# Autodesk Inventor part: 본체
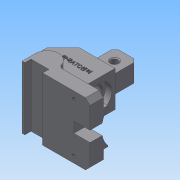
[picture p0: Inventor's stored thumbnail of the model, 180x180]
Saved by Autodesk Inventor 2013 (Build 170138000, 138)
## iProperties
Created: 2016-11
Part Number: 본체
Material: 일반
Document SubType Name: Modeling
Designer: Administrator
Density: 1 g/cm^3
Author: Administrator
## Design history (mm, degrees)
sketch "스케치1"
  geometry: L1 (-40.5, 0)-(-22.5, 18); L2 (-22.5, 18)-(17.5, 18); L3 (17.5, 18)-(17.5, -22); L4 (49.5, -30)-(-40.5, -30); L5 (-40.5, -30)-(-40.5, 0); L6 (49.5, -30)-(49.5, -22); L7 (49.5, -22)-(17.5, -22); 1 further point
  constraints: 14 end point, 4 perpendicular, 1 horizontal, 1 parallel
  dimensions: "d0" = 58 distance between parallel lines of L3 L5; "d2" = 48 distance between parallel lines of L4 L2; "d3" = 30 distance from line of L4 point (0, 0); "d4" = 17.5 distance from line of point (0, 0) L3; "d5" = 45 deg angle of L2 L1; "d6" = 18 horizontal distance of L1.start L1.end; "d28" = 90 distance of L4.start L4.end; "d30" = 40 distance between parallel lines of L7 L2
extrude "돌출1" new body sketch "스케치1" stored distance "d7" = 40; taper "d8" = 0 deg
sketch "스케치2"
  geometry: 2 further points
  constraints: 1 coincident
hole "구멍1" sketch "스케치2" at (20, 30) diameter "d10" = 20; stored, may be unused: countersink angle "d14" = 90 deg, drill point angle "d16" = 0 deg; dims "d11" = 6, "d12" = 29, "d13" = 7, "d15" = 8
sketch "스케치3"
  geometry: L1 (-26.5, -27)-(-26.5, -42); L2 (-26.5, -42)-(-23.5, -42); L3 (-23.5, -42)-(-23.5, -35); L4 (-23.5, -35)-(-3.5, -35); L5 (-3.5, -35)-(-3.5, -42); L6 (-3.5, -42)-(49.5, -42); L7 (49.5, -42)-(49.5, -27); L8 (49.5, -27)-(-0.5, -27); L9 (49.5, -22)-(49.5, -30) reference; A1 r 13 centre (-13.5, -27) between (-0.5, -27) and (-26.5, -27); 1 further point
  constraints: 16 end point, 3 collinear, 3 parallel, 3 perpendicular, 2 point on circle, 1 centre point, 1 horizontal alignment, 1 tangent, 1 vertical
  dimensions: "d17" = 26 diameter of A1; "d18" = 15 distance of L6.end L7.end; "d19" = 42 distance from line of L6 point (0, 0); "d20" = 20 distance between parallel lines of L5 L3; "d21" = 7 distance between parallel lines of L2 L4; "d22" = 3 distance of L1.end L2.end; "d25" = 63 distance from line of L7 A1.centre
extrude "돌출2" join sketch "스케치3" stored distance "d26" = 70; taper "d27" = 0 deg
sketch "스케치4"
  geometry: L1 (-15, -20)-(55, -20) reference; L2 (14, -6.373)-(14, -20); L3 (26, -6.373)-(26, -20); L4 (14, -20)-(26, -20); A1 r 29 centre (20, 22) between (26, -6.373) and (14, -6.373); 2 further points
  constraints: 6 end point, 2 perpendicular, 2 point on circle, 2 point on line, 1 centre point, 1 coincident, 1 collinear, 1 midpoint, 1 vertical alignment
  dimensions: "d31" = 58 diameter of A1; "d32" = 12 distance between parallel lines of L3 L2
extrude "돌출3" cut sketch "스케치4" distance "d33" = 18; taper "d34" = 0 deg
sketch "스케치5"
  geometry: L1 (-12.5, 48)-(12.5, 48); L2 (12.5, 48)-(12.5, 18); L3 (12.5, 18)-(-12.5, 18); L4 (-12.5, 18)-(-12.5, 48); L5 (-22.5, 18)-(17.5, 18) reference; L6 (49.5, -42)-(-3.5, -42) reference; 2 further points
  constraints: 8 end point, 2 parallel, 1 collinear, 1 horizontal, 1 midpoint, 1 perpendicular, 1 vertical alignment
  dimensions: "d35" = 25 distance of L1.start L1.end; "d37" = 90 distance between parallel lines of L6 L1
extrude "돌출4" join sketch "스케치5" stored distance "d38" = 20; taper "d39" = 0 deg
sketch "스케치6"
  geometry: C1 r 4 at (0, 35); 1 further point
  constraints: 1 centre point, 1 vertical alignment
  dimensions: "d40" = 8 diameter of C1; "d42" = 35 distance of point (0, 0) C1.centre
extrude "돌출5" cut sketch "스케치6" stored distance "d43" = 20; taper "d44" = 0 deg
chamfer "모따기1" distance "d45" = 4; stored, may be unused: second distance "d46" = 2, angle "d47" = 45 deg
chamfer "모따기2" distance "d48" = 5; stored, may be unused: second distance "d49" = 2, angle "d50" = 45 deg
chamfer "모따기3" distance "d51" = 1; stored, may be unused: second distance "d52" = 2, angle "d53" = 45 deg
fillet "모깎기1" dims "d54" = 3, "d55" = 5
sketch "스케치7"
  geometry: L1 (0, 0)-(0, 10) reference; 2 further points
  dimensions: "d56" = 18 distance from line of L1 point (-18, 2.5); "d57" = 27.5 vertical distance of point (-49.5, 30) point (-18, 2.5)
hole "구멍2" sketch "스케치7" at (-18, 2.5) diameter "d58" = 3.242; stored, may be unused: countersink angle "d62" = 90 deg, drill point angle "d64" = 0 deg; dims "d59" = 15, "d60" = 29, "d61" = 7, "d63" = 15
sketch "스케치8"
  geometry: L1 (17.5, 18)-(-22.5, 18) reference; 2 further points
  constraints: 1 other
  dimensions: "d65" = 18 distance from line of L1 point (-7.5, 0); "d66" = 25 horizontal distance of L1.start point (-7.5, 0)
feature "엠보싱1" sketch "스케치8" dims "d2" = 48, "d17" = 26, "d18" = 15, "d19" = 42, "d20" = 20, "d21" = 7, "d22" = 3, "d25" = 63, "d67" = 0.5, "d68" = 0
node "솔리드1"
mirror "대칭1"
